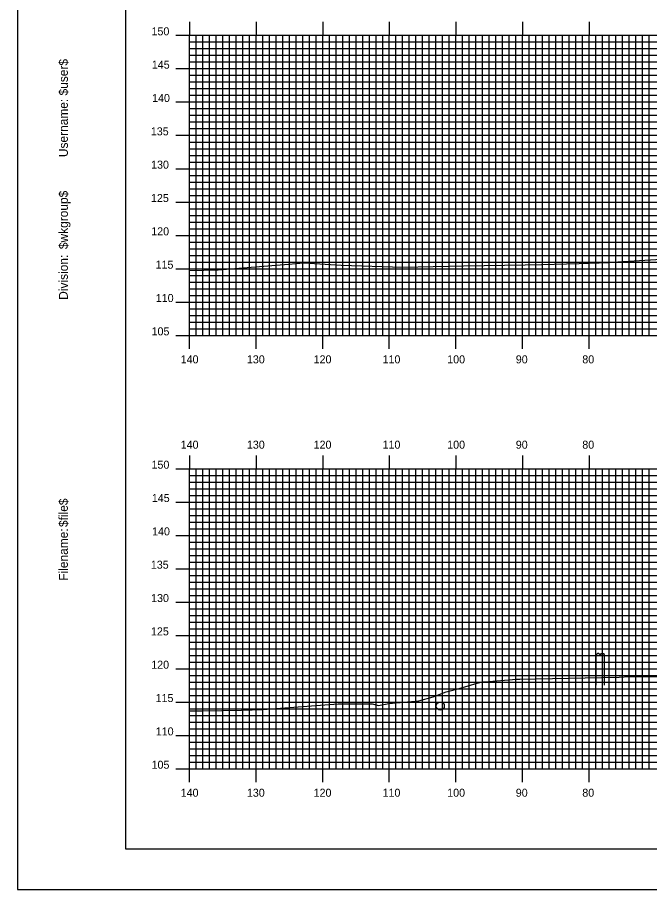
# Model space of a CAD drawing. Extents: x 1790124 to 1790467, y 442591 to 442811.
# Drawn here: x 1790123.9 to 1790218.7, y 442590.5 to 442721.4 of the extents above; entities that cross this region are included whole.
import ezdxf

# ---------------------------------------------------------------- set-up
doc = ezdxf.new("R2010")
doc.units = 0
for name, color, linetype in [('BORDER', 7, 'Continuous'), ('H_V ANNOTATION', 7, 'Continuous'), ('MAJOR', 7, 'Continuous'), ('MINOR', 7, 'Continuous'), ('PLOT BOUNDARY', 7, 'Continuous'), ('S_Drainage_Invert', 7, 'Continuous'), ('S_Roadway_Centerline', 7, 'Continuous'), ('S_Utilities_Pole_Power', 7, 'Continuous')]:
    doc.layers.add(name, color=color, linetype=linetype)

msp = doc.modelspace()

# ---------------------------------------------------------------- linework, layer by layer
at = {"layer": 'BORDER'}
msp.add_lwpolyline([(1790140.1, 442596.67), (1790460.1, 442596.67), (1790460.1, 442806.67), (1790140.1, 442806.67)], close=True, dxfattribs=at)
at = {"layer": 'MAJOR'}
for p, q in [((1790149.7, 442720.67), (1790149.7, 442718.67)), ((1790159.7, 442720.67), (1790159.7, 442718.67)), ((1790169.7, 442720.67), (1790169.7, 442718.67)), ((1790179.7, 442720.67), (1790179.7, 442718.67)), ((1790189.7, 442720.67), (1790189.7, 442718.67)), ((1790199.7, 442720.67), (1790199.7, 442718.67)), ((1790209.7, 442720.67), (1790209.7, 442718.67)), ((1790147.69, 442718.67), (1790149.7, 442718.67)), ((1790149.7, 442718.67), (1790429.7, 442718.67)), ((1790149.7, 442673.67), (1790149.7, 442718.67)), ((1790149.7, 442673.67), (1790149.7, 442718.67)), ((1790149.7, 442718.67), (1790429.7, 442718.67)), ((1790159.7, 442673.67), (1790159.7, 442718.67)), ((1790169.7, 442673.67), (1790169.7, 442718.67)), ((1790179.7, 442673.67), (1790179.7, 442718.67)), ((1790189.7, 442673.67), (1790189.7, 442718.67)), ((1790199.7, 442673.67), (1790199.7, 442718.67)), ((1790209.7, 442673.67), (1790209.7, 442718.67)), ((1790147.69, 442713.67), (1790149.7, 442713.67)), ((1790149.7, 442713.67), (1790429.7, 442713.67)), ((1790147.69, 442708.67), (1790149.7, 442708.67)), ((1790149.7, 442708.67), (1790429.7, 442708.67)), ((1790147.69, 442703.67), (1790149.7, 442703.67)), ((1790149.7, 442703.67), (1790429.7, 442703.67)), ((1790147.69, 442698.67), (1790149.7, 442698.67)), ((1790149.7, 442698.67), (1790429.7, 442698.67)), ((1790147.69, 442693.67), (1790149.7, 442693.67)), ((1790149.7, 442693.67), (1790429.7, 442693.67)), ((1790147.69, 442688.67), (1790149.7, 442688.67)), ((1790149.7, 442688.67), (1790429.7, 442688.67)), ((1790147.69, 442683.67), (1790149.7, 442683.67)), ((1790149.7, 442683.67), (1790429.7, 442683.67)), ((1790147.69, 442678.67), (1790149.7, 442678.67)), ((1790149.7, 442678.67), (1790429.7, 442678.67)), ((1790147.69, 442673.67), (1790149.7, 442673.67)), ((1790149.7, 442673.67), (1790429.7, 442673.67)), ((1790149.7, 442673.67), (1790429.7, 442673.67)), ((1790149.7, 442671.66), (1790149.7, 442673.67)), ((1790159.7, 442671.66), (1790159.7, 442673.67)), ((1790169.7, 442671.66), (1790169.7, 442673.67)), ((1790179.7, 442671.66), (1790179.7, 442673.67)), ((1790189.7, 442671.66), (1790189.7, 442673.67)), ((1790199.7, 442671.66), (1790199.7, 442673.67)), ((1790209.7, 442671.66), (1790209.7, 442673.67)), ((1790149.7, 442655.67), (1790149.7, 442653.67)), ((1790159.7, 442655.67), (1790159.7, 442653.67)), ((1790169.7, 442655.67), (1790169.7, 442653.67)), ((1790179.7, 442655.67), (1790179.7, 442653.67)), ((1790189.7, 442655.67), (1790189.7, 442653.67)), ((1790199.7, 442655.67), (1790199.7, 442653.67)), ((1790209.7, 442655.67), (1790209.7, 442653.67)), ((1790147.69, 442653.67), (1790149.7, 442653.67)), ((1790149.7, 442653.67), (1790429.7, 442653.67)), ((1790149.7, 442608.67), (1790149.7, 442653.67)), ((1790149.7, 442608.67), (1790149.7, 442653.67)), ((1790149.7, 442653.67), (1790429.7, 442653.67)), ((1790159.7, 442608.67), (1790159.7, 442653.67)), ((1790169.7, 442608.67), (1790169.7, 442653.67)), ((1790179.7, 442608.67), (1790179.7, 442653.67)), ((1790189.7, 442608.67), (1790189.7, 442653.67)), ((1790199.7, 442608.67), (1790199.7, 442653.67)), ((1790209.7, 442608.67), (1790209.7, 442653.67)), ((1790147.69, 442648.67), (1790149.7, 442648.67)), ((1790149.7, 442648.67), (1790429.7, 442648.67)), ((1790147.69, 442643.67), (1790149.7, 442643.67)), ((1790149.7, 442643.67), (1790429.7, 442643.67)), ((1790147.69, 442638.67), (1790149.7, 442638.67)), ((1790149.7, 442638.67), (1790429.7, 442638.67)), ((1790147.69, 442633.67), (1790149.7, 442633.67)), ((1790149.7, 442633.67), (1790429.7, 442633.67)), ((1790147.69, 442628.67), (1790149.7, 442628.67)), ((1790149.7, 442628.67), (1790429.7, 442628.67)), ((1790147.69, 442623.67), (1790149.7, 442623.67)), ((1790149.7, 442623.67), (1790429.7, 442623.67)), ((1790147.69, 442618.67), (1790149.7, 442618.67)), ((1790149.7, 442618.67), (1790429.7, 442618.67)), ((1790147.69, 442613.67), (1790149.7, 442613.67)), ((1790149.7, 442613.67), (1790429.7, 442613.67)), ((1790147.69, 442608.67), (1790149.7, 442608.67)), ((1790149.7, 442608.67), (1790429.7, 442608.67)), ((1790149.7, 442608.67), (1790429.7, 442608.67)), ((1790149.7, 442606.66), (1790149.7, 442608.67)), ((1790159.7, 442606.66), (1790159.7, 442608.67)), ((1790169.7, 442606.66), (1790169.7, 442608.67)), ((1790179.7, 442606.66), (1790179.7, 442608.67)), ((1790189.7, 442606.66), (1790189.7, 442608.67)), ((1790199.7, 442606.66), (1790199.7, 442608.67)), ((1790209.7, 442606.66), (1790209.7, 442608.67))]:
    msp.add_line(p, q, dxfattribs=at)
at = {"layer": 'MINOR'}
for p, q in [((1790149.7, 442717.67), (1790429.7, 442717.67)), ((1790149.7, 442717.67), (1790151.7, 442717.67)), ((1790150.7, 442673.67), (1790150.7, 442718.67)), ((1790151.7, 442673.67), (1790151.7, 442718.67)), ((1790152.7, 442673.67), (1790152.7, 442718.67)), ((1790153.7, 442673.67), (1790153.7, 442718.67)), ((1790154.7, 442673.67), (1790154.7, 442718.67)), ((1790155.7, 442673.67), (1790155.7, 442718.67)), ((1790156.7, 442673.67), (1790156.7, 442718.67)), ((1790157.7, 442673.67), (1790157.7, 442718.67)), ((1790158.7, 442673.67), (1790158.7, 442718.67)), ((1790160.7, 442673.67), (1790160.7, 442718.67)), ((1790161.7, 442673.67), (1790161.7, 442718.67)), ((1790162.7, 442673.67), (1790162.7, 442718.67)), ((1790163.7, 442673.67), (1790163.7, 442718.67)), ((1790164.7, 442673.67), (1790164.7, 442718.67)), ((1790165.7, 442673.67), (1790165.7, 442718.67)), ((1790166.7, 442673.67), (1790166.7, 442718.67)), ((1790167.7, 442673.67), (1790167.7, 442718.67)), ((1790168.7, 442673.67), (1790168.7, 442718.67)), ((1790170.7, 442673.67), (1790170.7, 442718.67)), ((1790171.7, 442673.67), (1790171.7, 442718.67)), ((1790172.7, 442673.67), (1790172.7, 442718.67)), ((1790173.7, 442673.67), (1790173.7, 442718.67)), ((1790174.7, 442673.67), (1790174.7, 442718.67)), ((1790175.7, 442673.67), (1790175.7, 442718.67)), ((1790176.7, 442673.67), (1790176.7, 442718.67)), ((1790177.7, 442673.67), (1790177.7, 442718.67)), ((1790178.7, 442673.67), (1790178.7, 442718.67)), ((1790180.7, 442673.67), (1790180.7, 442718.67)), ((1790181.7, 442673.67), (1790181.7, 442718.67)), ((1790182.7, 442673.67), (1790182.7, 442718.67)), ((1790183.7, 442673.67), (1790183.7, 442718.67)), ((1790184.7, 442673.67), (1790184.7, 442718.67)), ((1790185.7, 442673.67), (1790185.7, 442718.67)), ((1790186.7, 442673.67), (1790186.7, 442718.67)), ((1790187.7, 442673.67), (1790187.7, 442718.67)), ((1790188.7, 442673.67), (1790188.7, 442718.67)), ((1790190.7, 442673.67), (1790190.7, 442718.67)), ((1790191.7, 442673.67), (1790191.7, 442718.67)), ((1790192.7, 442673.67), (1790192.7, 442718.67)), ((1790193.7, 442673.67), (1790193.7, 442718.67)), ((1790194.7, 442673.67), (1790194.7, 442718.67)), ((1790195.7, 442673.67), (1790195.7, 442718.67)), ((1790196.7, 442673.67), (1790196.7, 442718.67)), ((1790197.7, 442673.67), (1790197.7, 442718.67)), ((1790198.7, 442673.67), (1790198.7, 442718.67)), ((1790200.7, 442673.67), (1790200.7, 442718.67)), ((1790201.7, 442673.67), (1790201.7, 442718.67)), ((1790202.7, 442673.67), (1790202.7, 442718.67)), ((1790203.7, 442673.67), (1790203.7, 442718.67)), ((1790204.7, 442673.67), (1790204.7, 442718.67)), ((1790205.7, 442673.67), (1790205.7, 442718.67)), ((1790206.7, 442673.67), (1790206.7, 442718.67)), ((1790207.7, 442673.67), (1790207.7, 442718.67)), ((1790208.7, 442673.67), (1790208.7, 442718.67)), ((1790210.7, 442673.67), (1790210.7, 442718.67)), ((1790211.7, 442673.67), (1790211.7, 442718.67)), ((1790212.7, 442673.67), (1790212.7, 442718.67)), ((1790213.7, 442673.67), (1790213.7, 442718.67)), ((1790214.7, 442673.67), (1790214.7, 442718.67)), ((1790215.7, 442673.67), (1790215.7, 442718.67)), ((1790216.7, 442673.67), (1790216.7, 442718.67)), ((1790217.7, 442673.67), (1790217.7, 442718.67)), ((1790218.7, 442673.67), (1790218.7, 442718.67)), ((1790149.7, 442716.67), (1790429.7, 442716.67)), ((1790149.7, 442716.67), (1790151.7, 442716.67)), ((1790149.7, 442715.67), (1790429.7, 442715.67)), ((1790149.7, 442715.67), (1790151.7, 442715.67)), ((1790149.7, 442714.67), (1790429.7, 442714.67)), ((1790149.7, 442714.67), (1790151.7, 442714.67)), ((1790149.7, 442712.67), (1790429.7, 442712.67)), ((1790149.7, 442712.67), (1790151.7, 442712.67)), ((1790149.7, 442711.67), (1790429.7, 442711.67)), ((1790149.7, 442711.67), (1790151.7, 442711.67)), ((1790149.7, 442710.67), (1790429.7, 442710.67)), ((1790149.7, 442710.67), (1790151.7, 442710.67)), ((1790149.7, 442709.67), (1790429.7, 442709.67)), ((1790149.7, 442709.67), (1790151.7, 442709.67)), ((1790149.7, 442707.67), (1790429.7, 442707.67)), ((1790149.7, 442707.67), (1790151.7, 442707.67)), ((1790149.7, 442706.67), (1790429.7, 442706.67)), ((1790149.7, 442706.67), (1790151.7, 442706.67)), ((1790149.7, 442705.67), (1790429.7, 442705.67)), ((1790149.7, 442705.67), (1790151.7, 442705.67)), ((1790149.7, 442704.67), (1790429.7, 442704.67)), ((1790149.7, 442704.67), (1790151.7, 442704.67)), ((1790149.7, 442702.67), (1790429.7, 442702.67)), ((1790149.7, 442702.67), (1790151.7, 442702.67)), ((1790149.7, 442701.67), (1790429.7, 442701.67)), ((1790149.7, 442701.67), (1790151.7, 442701.67)), ((1790149.7, 442700.67), (1790429.7, 442700.67)), ((1790149.7, 442700.67), (1790151.7, 442700.67)), ((1790149.7, 442699.67), (1790429.7, 442699.67)), ((1790149.7, 442699.67), (1790151.7, 442699.67)), ((1790149.7, 442697.67), (1790429.7, 442697.67)), ((1790149.7, 442697.67), (1790151.7, 442697.67)), ((1790149.7, 442696.67), (1790429.7, 442696.67)), ((1790149.7, 442696.67), (1790151.7, 442696.67)), ((1790149.7, 442695.67), (1790429.7, 442695.67)), ((1790149.7, 442695.67), (1790151.7, 442695.67)), ((1790149.7, 442694.67), (1790429.7, 442694.67)), ((1790149.7, 442694.67), (1790151.7, 442694.67)), ((1790149.7, 442692.67), (1790429.7, 442692.67)), ((1790149.7, 442692.67), (1790151.7, 442692.67)), ((1790149.7, 442691.67), (1790429.7, 442691.67)), ((1790149.7, 442691.67), (1790151.7, 442691.67)), ((1790149.7, 442690.67), (1790429.7, 442690.67)), ((1790149.7, 442690.67), (1790151.7, 442690.67)), ((1790149.7, 442689.67), (1790429.7, 442689.67)), ((1790149.7, 442689.67), (1790151.7, 442689.67)), ((1790149.7, 442687.67), (1790429.7, 442687.67)), ((1790149.7, 442687.67), (1790151.7, 442687.67)), ((1790149.7, 442686.67), (1790429.7, 442686.67)), ((1790149.7, 442686.67), (1790151.7, 442686.67)), ((1790149.7, 442685.67), (1790429.7, 442685.67)), ((1790149.7, 442685.67), (1790151.7, 442685.67)), ((1790149.7, 442684.67), (1790429.7, 442684.67)), ((1790149.7, 442684.67), (1790151.7, 442684.67)), ((1790149.7, 442682.67), (1790429.7, 442682.67)), ((1790149.7, 442682.67), (1790151.7, 442682.67)), ((1790149.7, 442681.67), (1790429.7, 442681.67)), ((1790149.7, 442681.67), (1790151.7, 442681.67)), ((1790149.7, 442680.67), (1790429.7, 442680.67)), ((1790149.7, 442680.67), (1790151.7, 442680.67)), ((1790149.7, 442679.67), (1790429.7, 442679.67)), ((1790149.7, 442679.67), (1790151.7, 442679.67)), ((1790149.7, 442677.67), (1790429.7, 442677.67)), ((1790149.7, 442677.67), (1790151.7, 442677.67)), ((1790149.7, 442676.67), (1790429.7, 442676.67)), ((1790149.7, 442676.67), (1790151.7, 442676.67)), ((1790149.7, 442675.67), (1790429.7, 442675.67)), ((1790149.7, 442675.67), (1790151.7, 442675.67)), ((1790149.7, 442674.67), (1790429.7, 442674.67)), ((1790149.7, 442674.67), (1790151.7, 442674.67)), ((1790150.7, 442608.67), (1790150.7, 442653.67)), ((1790151.7, 442608.67), (1790151.7, 442653.67)), ((1790152.7, 442608.67), (1790152.7, 442653.67)), ((1790153.7, 442608.67), (1790153.7, 442653.67)), ((1790154.7, 442608.67), (1790154.7, 442653.67)), ((1790155.7, 442608.67), (1790155.7, 442653.67)), ((1790156.7, 442608.67), (1790156.7, 442653.67)), ((1790157.7, 442608.67), (1790157.7, 442653.67)), ((1790158.7, 442608.67), (1790158.7, 442653.67)), ((1790160.7, 442608.67), (1790160.7, 442653.67)), ((1790161.7, 442608.67), (1790161.7, 442653.67)), ((1790162.7, 442608.67), (1790162.7, 442653.67)), ((1790163.7, 442608.67), (1790163.7, 442653.67)), ((1790164.7, 442608.67), (1790164.7, 442653.67)), ((1790165.7, 442608.67), (1790165.7, 442653.67)), ((1790166.7, 442608.67), (1790166.7, 442653.67)), ((1790167.7, 442608.67), (1790167.7, 442653.67)), ((1790168.7, 442608.67), (1790168.7, 442653.67)), ((1790170.7, 442608.67), (1790170.7, 442653.67)), ((1790171.7, 442608.67), (1790171.7, 442653.67)), ((1790172.7, 442608.67), (1790172.7, 442653.67)), ((1790173.7, 442608.67), (1790173.7, 442653.67)), ((1790174.7, 442608.67), (1790174.7, 442653.67)), ((1790175.7, 442608.67), (1790175.7, 442653.67)), ((1790176.7, 442608.67), (1790176.7, 442653.67)), ((1790177.7, 442608.67), (1790177.7, 442653.67)), ((1790178.7, 442608.67), (1790178.7, 442653.67)), ((1790180.7, 442608.67), (1790180.7, 442653.67)), ((1790181.7, 442608.67), (1790181.7, 442653.67)), ((1790182.7, 442608.67), (1790182.7, 442653.67)), ((1790183.7, 442608.67), (1790183.7, 442653.67)), ((1790184.7, 442608.67), (1790184.7, 442653.67)), ((1790185.7, 442608.67), (1790185.7, 442653.67)), ((1790186.7, 442608.67), (1790186.7, 442653.67)), ((1790187.7, 442608.67), (1790187.7, 442653.67)), ((1790188.7, 442608.67), (1790188.7, 442653.67)), ((1790190.7, 442608.67), (1790190.7, 442653.67)), ((1790191.7, 442608.67), (1790191.7, 442653.67)), ((1790192.7, 442608.67), (1790192.7, 442653.67)), ((1790193.7, 442608.67), (1790193.7, 442653.67)), ((1790194.7, 442608.67), (1790194.7, 442653.67)), ((1790195.7, 442608.67), (1790195.7, 442653.67)), ((1790196.7, 442608.67), (1790196.7, 442653.67)), ((1790197.7, 442608.67), (1790197.7, 442653.67)), ((1790198.7, 442608.67), (1790198.7, 442653.67)), ((1790200.7, 442608.67), (1790200.7, 442653.67)), ((1790201.7, 442608.67), (1790201.7, 442653.67)), ((1790202.7, 442608.67), (1790202.7, 442653.67)), ((1790203.7, 442608.67), (1790203.7, 442653.67)), ((1790204.7, 442608.67), (1790204.7, 442653.67)), ((1790205.7, 442608.67), (1790205.7, 442653.67)), ((1790206.7, 442608.67), (1790206.7, 442653.67)), ((1790207.7, 442608.67), (1790207.7, 442653.67)), ((1790208.7, 442608.67), (1790208.7, 442653.67)), ((1790210.7, 442608.67), (1790210.7, 442653.67)), ((1790211.7, 442608.67), (1790211.7, 442653.67)), ((1790212.7, 442608.67), (1790212.7, 442653.67)), ((1790213.7, 442608.67), (1790213.7, 442653.67)), ((1790214.7, 442608.67), (1790214.7, 442653.67)), ((1790215.7, 442608.67), (1790215.7, 442653.67)), ((1790216.7, 442608.67), (1790216.7, 442653.67)), ((1790217.7, 442608.67), (1790217.7, 442653.67)), ((1790218.7, 442608.67), (1790218.7, 442653.67)), ((1790149.7, 442652.67), (1790429.7, 442652.67)), ((1790149.7, 442652.67), (1790151.7, 442652.67)), ((1790149.7, 442651.67), (1790429.7, 442651.67)), ((1790149.7, 442651.67), (1790151.7, 442651.67)), ((1790149.7, 442650.67), (1790429.7, 442650.67)), ((1790149.7, 442650.67), (1790151.7, 442650.67)), ((1790149.7, 442649.67), (1790429.7, 442649.67)), ((1790149.7, 442649.67), (1790151.7, 442649.67)), ((1790149.7, 442647.67), (1790429.7, 442647.67)), ((1790149.7, 442647.67), (1790151.7, 442647.67)), ((1790149.7, 442646.67), (1790429.7, 442646.67)), ((1790149.7, 442646.67), (1790151.7, 442646.67)), ((1790149.7, 442645.67), (1790429.7, 442645.67)), ((1790149.7, 442645.67), (1790151.7, 442645.67)), ((1790149.7, 442644.67), (1790429.7, 442644.67)), ((1790149.7, 442644.67), (1790151.7, 442644.67)), ((1790149.7, 442642.67), (1790429.7, 442642.67)), ((1790149.7, 442642.67), (1790151.7, 442642.67)), ((1790149.7, 442641.67), (1790429.7, 442641.67)), ((1790149.7, 442641.67), (1790151.7, 442641.67)), ((1790149.7, 442640.67), (1790429.7, 442640.67)), ((1790149.7, 442640.67), (1790151.7, 442640.67)), ((1790149.7, 442639.67), (1790429.7, 442639.67)), ((1790149.7, 442639.67), (1790151.7, 442639.67)), ((1790149.7, 442637.67), (1790429.7, 442637.67)), ((1790149.7, 442637.67), (1790151.7, 442637.67)), ((1790149.7, 442636.67), (1790429.7, 442636.67)), ((1790149.7, 442636.67), (1790151.7, 442636.67)), ((1790149.7, 442635.67), (1790429.7, 442635.67)), ((1790149.7, 442635.67), (1790151.7, 442635.67)), ((1790149.7, 442634.67), (1790429.7, 442634.67)), ((1790149.7, 442634.67), (1790151.7, 442634.67)), ((1790149.7, 442632.67), (1790429.7, 442632.67)), ((1790149.7, 442632.67), (1790151.7, 442632.67)), ((1790149.7, 442631.67), (1790429.7, 442631.67)), ((1790149.7, 442631.67), (1790151.7, 442631.67)), ((1790149.7, 442630.67), (1790429.7, 442630.67)), ((1790149.7, 442630.67), (1790151.7, 442630.67)), ((1790149.7, 442629.67), (1790429.7, 442629.67)), ((1790149.7, 442629.67), (1790151.7, 442629.67)), ((1790149.7, 442627.67), (1790429.7, 442627.67)), ((1790149.7, 442627.67), (1790151.7, 442627.67)), ((1790149.7, 442626.67), (1790429.7, 442626.67)), ((1790149.7, 442626.67), (1790151.7, 442626.67)), ((1790149.7, 442625.67), (1790429.7, 442625.67)), ((1790149.7, 442625.67), (1790151.7, 442625.67)), ((1790149.7, 442624.67), (1790429.7, 442624.67)), ((1790149.7, 442624.67), (1790151.7, 442624.67)), ((1790149.7, 442622.67), (1790429.7, 442622.67)), ((1790149.7, 442622.67), (1790151.7, 442622.67)), ((1790149.7, 442621.67), (1790429.7, 442621.67)), ((1790149.7, 442621.67), (1790151.7, 442621.67)), ((1790149.7, 442620.67), (1790429.7, 442620.67)), ((1790149.7, 442620.67), (1790151.7, 442620.67)), ((1790149.7, 442619.67), (1790429.7, 442619.67)), ((1790149.7, 442619.67), (1790151.7, 442619.67)), ((1790149.7, 442617.67), (1790429.7, 442617.67)), ((1790149.7, 442617.67), (1790151.7, 442617.67)), ((1790149.7, 442616.67), (1790429.7, 442616.67)), ((1790149.7, 442616.67), (1790151.7, 442616.67)), ((1790149.7, 442615.67), (1790429.7, 442615.67)), ((1790149.7, 442615.67), (1790151.7, 442615.67)), ((1790149.7, 442614.67), (1790429.7, 442614.67)), ((1790149.7, 442614.67), (1790151.7, 442614.67)), ((1790149.7, 442612.67), (1790429.7, 442612.67)), ((1790149.7, 442612.67), (1790151.7, 442612.67)), ((1790149.7, 442611.67), (1790429.7, 442611.67)), ((1790149.7, 442611.67), (1790151.7, 442611.67)), ((1790149.7, 442610.67), (1790429.7, 442610.67)), ((1790149.7, 442610.67), (1790151.7, 442610.67)), ((1790149.7, 442609.67), (1790429.7, 442609.67)), ((1790149.7, 442609.67), (1790151.7, 442609.67))]:
    msp.add_line(p, q, dxfattribs=at)
at = {"layer": 'PLOT BOUNDARY'}
msp.add_lwpolyline([(1790123.91, 442590.55), (1790463.91, 442590.55), (1790463.91, 442810.55), (1790123.91, 442810.55)], close=True, dxfattribs=at)
at = {"layer": 'S_Drainage_Invert'}
msp.add_circle((1790187.35, 442618.07), 0.6, dxfattribs=at)
at = {"layer": 'S_Roadway_Centerline'}
for points in [[(1790149.7, 442683.4), (1790154.04, 442683.51), (1790164.55, 442684.37), (1790166.86, 442684.55), (1790172.48, 442684.22), (1790181.73, 442683.92), (1790190.83, 442684.08), (1790200.06, 442684.24), (1790202.55, 442684.31), (1790208.19, 442684.46), (1790212.68, 442684.61), (1790213.96, 442684.69), (1790222.91, 442685.25)], [(1790149.7, 442617.36), (1790151.61, 442617.36), (1790157.53, 442617.46), (1790160.7, 442617.53), (1790172.01, 442618.39), (1790177.12, 442618.38), (1790178.07, 442618.15), (1790179.65, 442618.45), (1790184.13, 442618.84), (1790186.29, 442619.47), (1790188.25, 442620.18), (1790188.63, 442620.29), (1790188.63, 442620.28), (1790190.18, 442620.69), (1790192.88, 442621.48), (1790193.67, 442621.68), (1790194.03, 442621.71), (1790198.79, 442622.08), (1790199.26, 442622.12), (1790211.53, 442622.33), (1790214.2, 442622.4), (1790215.75, 442622.51), (1790220.02, 442622.44)]]:
    msp.add_lwpolyline(points, dxfattribs=at)
at = {"layer": 'S_Utilities_Pole_Power'}
for p, q in [((1790210.72, 442625.81), (1790210.88, 442625.92)), ((1790210.72, 442621.19), (1790210.72, 442625.81)), ((1790211.19, 442625.92), (1790211.34, 442625.81)), ((1790211.5, 442625.92), (1790211.34, 442625.81)), ((1790211.34, 442625.81), (1790211.5, 442625.7)), ((1790211.97, 442625.81), (1790211.81, 442625.92)), ((1790211.81, 442625.7), (1790211.97, 442625.81)), ((1790211.97, 442621.19), (1790211.97, 442625.81))]:
    msp.add_line(p, q, dxfattribs=at)
for centre, start, end in [((1790211.03, 442625.7), 90, 125.2644), ((1790211.03, 442625.7), 54.7356, 90), ((1790211.66, 442625.7), 90, 125.2644), ((1790211.66, 442625.92), 234.7356, 270), ((1790211.66, 442625.7), 54.7356, 90), ((1790211.66, 442625.92), 270, 305.2644)]:
    msp.add_arc(centre, 0.271, start, end, dxfattribs=at)

# ---------------------------------------------------------------- texts
at = {"layer": 'BORDER'}
for s, p in [('$user$', (1790131.47, 442709.65)), ('Username:', (1790131.47, 442700.4)), ('$wkgroup$', (1790131.47, 442686.6)), ('Division:', (1790131.47, 442679)), ('$file$', (1790131.47, 442644.92)), ('Filename:', (1790131.47, 442636.86))]:
    msp.add_text(s, height=1.339, rotation=90, dxfattribs=at).set_placement(p)
at = {"layer": 'H_V ANNOTATION'}
for s, p in [('150', (1790144.02, 442718.67)), ('145', (1790144.07, 442713.67)), ('140', (1790144.11, 442708.67)), ('135', (1790143.92, 442703.67)), ('130', (1790143.96, 442698.67)), ('125', (1790143.94, 442693.67)), ('120', (1790143.98, 442688.67)), ('115', (1790144.63, 442683.67)), ('110', (1790144.66, 442678.67)), ('105', (1790144.03, 442673.67)), ('140', (1790148.4, 442669.47)), ('130', (1790158.33, 442669.47)), ('120', (1790168.34, 442669.47)), ('110', (1790178.68, 442669.47)), ('100', (1790188.38, 442669.47)), ('90', (1790198.67, 442669.47)), ('80', (1790208.65, 442669.47)), ('140', (1790148.4, 442656.67)), ('130', (1790158.33, 442656.67)), ('120', (1790168.34, 442656.67)), ('110', (1790178.68, 442656.67)), ('100', (1790188.38, 442656.67)), ('90', (1790198.67, 442656.67)), ('80', (1790208.65, 442656.67)), ('150', (1790144.02, 442653.67)), ('145', (1790144.07, 442648.67)), ('140', (1790144.11, 442643.67)), ('135', (1790143.92, 442638.67)), ('130', (1790143.96, 442633.67)), ('125', (1790143.94, 442628.67)), ('120', (1790143.98, 442623.67)), ('115', (1790144.63, 442618.67)), ('110', (1790144.66, 442613.67)), ('105', (1790144.03, 442608.67)), ('140', (1790148.4, 442604.47)), ('130', (1790158.33, 442604.47)), ('120', (1790168.34, 442604.47)), ('110', (1790178.68, 442604.47)), ('100', (1790188.38, 442604.47)), ('90', (1790198.67, 442604.47)), ('80', (1790208.65, 442604.47))]:
    msp.add_text(s, height=1.2, dxfattribs=at).set_placement(p)
at = {"layer": 'MAJOR'}
for p in [(1790149.69, 442673.67), (1790149.69, 442608.67)]:
    msp.add_text('-', height=0.012, dxfattribs=at).set_placement(p)
at = {"layer": 'S_Roadway_Centerline'}
for s, p in [('C', (1790215.74, 442622.51)), ('C', (1790215.74, 442622.51)), ('L', (1790215.75, 442622.51)), ('L', (1790215.75, 442622.51))]:
    msp.add_text(s, height=0.0146, dxfattribs=at).set_placement(p)

doc.saveas('drawing.dxf')
